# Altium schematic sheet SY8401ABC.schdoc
size 127 x 101 mm
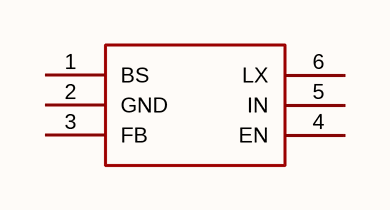
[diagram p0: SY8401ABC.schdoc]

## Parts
U?  sy8401abc  [SOT-23-6_L2.9-W1.6-P0.95-LS2.8-BR]  (value not drawn)

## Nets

Not connected (* = marked no-connect by the designer): U? 1(BS) 2(GND) 3(FB) 4(EN) 5(IN) 6(LX)

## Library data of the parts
U? = sy8401abc: 功能类型:降压型;工作电压:4.5V~50V;输出电压:-;输出电流:800mA;输出类型:可调;; Manufacturer: Silergy(矽力杰); AddInBom: yes; ModelId: 18da8f6c14a34920b3e136b5c401a119; ModelName: SOT-23-6_L2.9-W1.6-H1.5-LS2.8-P0.95; ModelTransform: 110.73671,114.173,0,180,0,0,0.001,-0.003,0; Function: 降压型; Output Current: 800mA; Frequency - Switching: 1.2MHz; Synchronous Rectifier: 否; Number of Outputs: 1; Topology: 降压式; Quiescent Current: 150uA; Switch tube (built-in/external): 内置; Output Type: 可调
